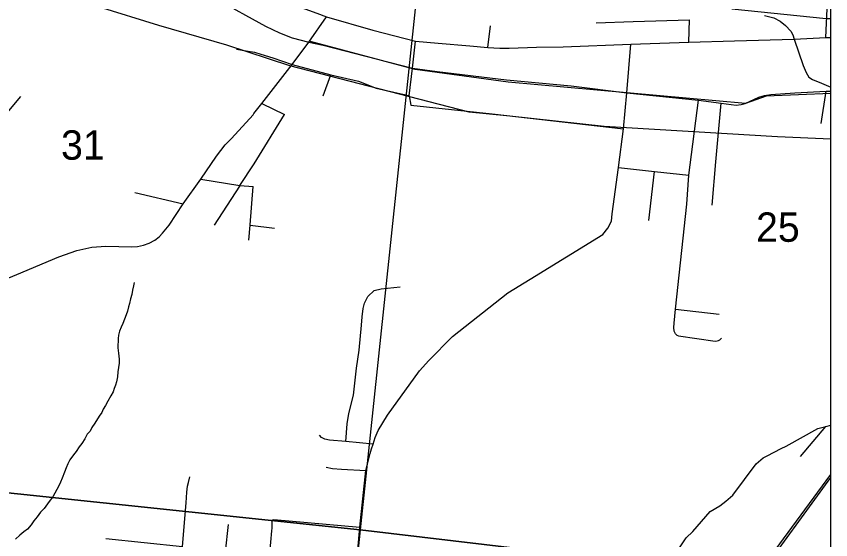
# Model space of a CAD drawing. Extents: x 0 to 34, y -2 to 22.
# Drawn here: x 7.738 to 8.9, y 17.461 to 18.207 of the extents above; entities that cross this region are included whole.
import ezdxf

# ---------------------------------------------------------------- set-up
doc = ezdxf.new("R2010")
doc.units = 0
for name, color, linetype in [('Default', 7, 'Continuous'), ('GM_X_City_Street', 7, 'Continuous'), ('GM_X_County_Road', 7, 'Continuous'), ('GM_X_Minor_River', 7, 'Continuous'), ('GM_X_Rail_Line', 7, 'Continuous'), ('GM_X_Section', 7, 'Continuous'), ('GM_X_Section_Text', 7, 'Continuous'), ('SH_Cut_Line', 7, 'Continuous')]:
    doc.layers.add(name, color=color, linetype=linetype)

msp = doc.modelspace()

# ---------------------------------------------------------------- linework, layer by layer
at = {"layer": 'Default'}
for points in [[(8.9, 17.3957), (8.9, 18.4149), (8.3344, 18.4751), (8.2288, 17.4754)], [(8.9, 16.3966), (8.9, 17.3957), (8.2288, 17.4754), (8.1243, 16.4653), (8.7506, 16.3888), (8.762, 16.3912), (8.7711, 16.3925), (8.792, 16.3947), (8.8076, 16.3958), (8.8333, 16.3964), (8.8504, 16.3971), (8.8879, 16.3966)]]:
    msp.add_lwpolyline(points, close=True, dxfattribs=at)
at = {"layer": 'GM_X_City_Street'}
for p, q in [((8.6978, 18.1706), (8.6983, 18.2023)), ((8.4109, 18.163), (8.4145, 18.1937)), ((8.1757, 18.0942), (8.1869, 18.124)), ((8.8865, 18.0548), (8.8934, 18.1006)), ((8.0882, 18.0833), (8.1208, 18.0673)), ((8.6403, 17.9165), (8.6486, 17.9863)), ((7.9071, 17.9561), (7.976, 17.9398)), ((8.0717, 17.9094), (8.1065, 17.9055)), ((8.6786, 17.7899), (8.7409, 17.7825)), ((8.8569, 17.5799), (8.8929, 17.6226)), ((8.1054, 17.4898), (8.228, 17.4791))]:
    msp.add_line(p, q, dxfattribs=at)
for points in [[(8.8931, 18.1772), (8.8963, 18.2495), (8.898, 18.2736), (8.9, 18.287)], [(8.5652, 18.1982), (8.618, 18.1999), (8.6983, 18.2023)], [(8.2986, 18.0938), (8.3032, 18.1336), (8.3078, 18.1718)], [(8.0523, 18.1605), (8.0658, 18.1581), (8.0778, 18.1565), (8.087, 18.1534), (8.104, 18.1481), (8.1315, 18.1388)], [(8.1315, 18.1388), (8.1869, 18.124), (8.2261, 18.115), (8.2516, 18.1049), (8.2916, 18.0961), (8.2986, 18.0938)], [(7.4663, 17.9186), (7.5384, 17.9251), (7.5903, 17.932), (7.6582, 17.941), (7.6604, 17.9416), (7.6635, 17.9429), (7.6669, 17.9452), (7.6708, 17.9489), (7.6721, 17.9509), (7.6728, 17.953), (7.6765, 17.989), (7.6792, 18.0052), (7.6968, 18.0333), (7.7178, 18.0613), (7.7446, 18.093)], [(8.2986, 18.0938), (8.301, 18.0806), (8.4172, 18.0684), (8.6044, 18.0469)], [(8.6784, 17.7547), (8.6765, 17.7583), (8.6764, 17.7637), (8.6768, 17.7697), (8.6786, 17.7899), (8.6946, 17.9397), (8.6978, 17.981), (8.7112, 18.0877)], [(8.7309, 17.9379), (8.7359, 18.0001), (8.7437, 18.0837)], [(8.021, 17.9098), (8.0568, 17.9654), (8.0572, 17.9661), (8.0772, 17.9971), (8.1208, 18.0673)], [(8.5971, 17.9918), (8.6486, 17.9863), (8.6978, 17.981)], [(8.0015, 17.9753), (8.0572, 17.9661), (8.0761, 17.9649)], [(8.07, 17.8884), (8.0717, 17.9094), (8.0717, 17.9103), (8.0761, 17.9649)], [(8.2084, 17.6013), (8.2101, 17.6265), (8.2125, 17.6411), (8.2193, 17.6672), (8.2236, 17.7057), (8.2273, 17.7313), (8.2306, 17.7672), (8.2314, 17.779), (8.2331, 17.7906), (8.2346, 17.7985), (8.2394, 17.8081), (8.2487, 17.8163), (8.2587, 17.8188), (8.2856, 17.8216)], [(8.6784, 17.7547), (8.6803, 17.7529), (8.683, 17.7517), (8.7353, 17.7443), (8.7379, 17.7445), (8.7398, 17.7451), (8.742, 17.7462), (8.7442, 17.7484)], [(8.6715, 17.4307), (8.6939, 17.4636), (8.7034, 17.473), (8.728, 17.5016), (8.7419, 17.5094), (8.7505, 17.516), (8.7603, 17.5248), (8.7936, 17.5692), (8.8035, 17.578), (8.8091, 17.5808), (8.8295, 17.5911), (8.8365, 17.5947), (8.8814, 17.6198), (8.8929, 17.6226), (8.9, 17.6243)], [(8.247, 17.5975), (8.2084, 17.6013), (8.1849, 17.6031), (8.1781, 17.6047), (8.1737, 17.607), (8.1705, 17.6104)], [(8.1802, 17.5644), (8.1892, 17.5625), (8.2018, 17.5615), (8.2368, 17.5597)], [(7.9504, 17.2143), (7.9504, 17.2176), (7.9509, 17.2234), (7.9607, 17.3157), (7.9752, 17.4513), (7.9806, 17.5136), (7.9813, 17.529), (7.9823, 17.5376), (7.9835, 17.5428), (7.9858, 17.551)], [(8.0612, 17.0667), (8.0744, 17.1973), (8.0848, 17.3028), (8.0991, 17.438), (8.101, 17.4576), (8.1025, 17.4738), (8.103, 17.4777), (8.1031, 17.4832), (8.1031, 17.4872), (8.1038, 17.4894), (8.1054, 17.4898)], [(7.976, 16.871), (7.9973, 17.0616), (7.9992, 17.0743), (8.012, 17.2021), (8.0237, 17.3088), (8.0365, 17.4437), (8.041, 17.4827)], [(7.866, 17.4629), (7.9752, 17.4513)]]:
    msp.add_lwpolyline(points, dxfattribs=at)
at = {"layer": 'GM_X_County_Road'}
for points in [[(8.0322, 18.2591), (8.0709, 18.2467), (8.1167, 18.2299), (8.1666, 18.2118), (8.1804, 18.2065), (8.2466, 18.1876), (8.3078, 18.1718), (8.3397, 18.169), (8.3851, 18.1652), (8.4109, 18.163), (8.4281, 18.1619), (8.4412, 18.1621), (8.4804, 18.1632), (8.5185, 18.164), (8.6148, 18.1677), (8.6978, 18.1706), (8.7625, 18.1723), (8.8479, 18.1749)], [(8.0225, 18.2329), (8.0937, 18.1933), (8.1135, 18.1836), (8.1317, 18.1768), (8.1552, 18.1704)], [(8.8055, 18.2086), (8.8187, 18.2053), (8.828, 18.2007), (8.8357, 18.1945), (8.8431, 18.1862), (8.8461, 18.181), (8.8479, 18.1749)], [(8.0769, 18.0686), (8.0882, 18.0833), (8.1315, 18.1388), (8.1552, 18.1704), (8.1804, 18.2065)], [(8.8479, 18.1749), (8.8931, 18.1772), (8.9, 18.1773)], [(8.8479, 18.1749), (8.8606, 18.1372), (8.8648, 18.1274), (8.869, 18.1207), (8.8741, 18.1171), (8.887, 18.1119), (8.9, 18.1066)], [(8.1552, 18.1704), (8.176, 18.1662), (8.2368, 18.1504), (8.3032, 18.1336), (8.3387, 18.1286), (8.4374, 18.117), (8.5295, 18.1081), (8.6091, 18.0985), (8.7112, 18.0877), (8.7437, 18.0837), (8.765, 18.0808), (8.7723, 18.0815), (8.7778, 18.0829), (8.7975, 18.0921), (8.8054, 18.0945), (8.8145, 18.0961), (8.8487, 18.0984), (8.8934, 18.1006), (8.9, 18.1006)], [(8.2234, 17.4245), (8.228, 17.4791), (8.2368, 17.5597), (8.2428, 17.5841), (8.2448, 17.5909), (8.247, 17.5975), (8.2502, 17.6069), (8.2545, 17.6168), (8.2678, 17.6389), (8.3131, 17.7019), (8.3264, 17.7167), (8.3606, 17.7511), (8.4393, 17.8131), (8.4713, 17.8324), (8.5748, 17.8962), (8.5822, 17.9052), (8.5874, 17.9154), (8.5883, 17.9256), (8.5971, 17.9918), (8.6044, 18.0469), (8.6091, 18.0985), (8.6148, 18.1677)], [(7.7072, 17.8263), (7.7388, 17.8395), (7.7987, 17.8644), (7.8242, 17.8736), (7.846, 17.8783), (7.8659, 17.8797), (7.9027, 17.8786), (7.9111, 17.8794), (7.9193, 17.881), (7.9274, 17.8839), (7.9356, 17.8881), (7.9419, 17.8931), (7.9468, 17.8983), (7.956, 17.9096), (7.976, 17.9398), (8.0015, 17.9753), (8.0236, 18.0081), (8.0362, 18.0242), (8.0451, 18.0334), (8.0758, 18.0671), (8.0769, 18.0686)], [(8.582, 16.7358), (8.5958, 16.7847), (8.6067, 16.8315), (8.613, 16.8584), (8.6291, 16.9179), (8.6344, 16.9724), (8.6414, 17.0222), (8.6589, 17.0461), (8.685, 17.0981), (8.715, 17.1789), (8.7208, 17.199), (8.755, 17.3171), (8.7589, 17.3326), (8.7699, 17.3755), (8.7743, 17.3825), (8.7929, 17.4086), (8.8207, 17.4464), (8.9, 17.5541)]]:
    msp.add_lwpolyline(points, dxfattribs=at)
at = {"layer": 'GM_X_Minor_River'}
msp.add_lwpolyline([(7.9063, 17.8278), (7.9051, 17.8229), (7.9038, 17.8168), (7.9028, 17.8107), (7.9008, 17.8047), (7.8995, 17.7979), (7.8982, 17.793), (7.8965, 17.7869), (7.8948, 17.7816), (7.8899, 17.7696), (7.8875, 17.764), (7.8855, 17.7587), (7.8838, 17.7526), (7.8833, 17.7481), (7.8829, 17.7348), (7.8838, 17.7271), (7.8848, 17.7187), (7.885, 17.713), (7.884, 17.7065), (7.8831, 17.7005), (7.8822, 17.6933), (7.8808, 17.6861), (7.8796, 17.6815), (7.8779, 17.6766), (7.8763, 17.6721), (7.8731, 17.6665), (7.8687, 17.6586), (7.8651, 17.6526), (7.8619, 17.6474), (7.8599, 17.6425), (7.8563, 17.6372), (7.8503, 17.6271), (7.8456, 17.6211), (7.8432, 17.6159), (7.8393, 17.6114), (7.8357, 17.605), (7.8317, 17.5983), (7.8278, 17.5938), (7.8234, 17.5871), (7.8195, 17.5823), (7.8143, 17.5752), (7.8115, 17.5695), (7.8091, 17.5635), (7.8066, 17.5575), (7.8033, 17.5488), (7.8009, 17.5432), (7.7985, 17.5379), (7.7901, 17.5221), (7.7849, 17.5158), (7.7778, 17.5057), (7.7727, 17.5002), (7.768, 17.4938), (7.7629, 17.4879), (7.7593, 17.4822), (7.7542, 17.4763), (7.7488, 17.4726), (7.7433, 17.4678), (7.7371, 17.4619)], dxfattribs=at)
at = {"layer": 'GM_X_Rail_Line'}
for points in [[(7.6912, 15.289), (7.9856, 15.5639), (8.2003, 15.8586), (8.2596, 15.9572), (8.5337, 16.2495), (8.6286, 16.3042), (8.7283, 16.3459), (8.827, 16.358), (8.9, 16.3574), (8.9, 20.9)], [(8.9, 18.0324), (8.8241, 18.0356), (8.5766, 18.0505), (8.4424, 18.0652), (8.3842, 18.0707), (8.1282, 18.1369), (8.0382, 18.1663), (7.9414, 18.1945), (7.8552, 18.2209)], [(8.9, 18.2038), (8.8934, 18.204), (8.7591, 18.2174)], [(8.9, 18.0972), (8.8081, 18.0934), (8.7782, 18.0831), (8.44, 18.1136), (8.3071, 18.1314), (8.156, 18.1718)], [(8.5802, 16.7346), (8.6309, 16.9422), (8.6388, 17.023), (8.6657, 17.0611), (8.697, 17.129), (8.7281, 17.2039), (8.7533, 17.2946), (8.7737, 17.3687), (8.7924, 17.4016), (8.9, 17.55)]]:
    msp.add_lwpolyline(points, dxfattribs=at)
at = {"layer": 'GM_X_Section'}
for points in [[(8.3344, 18.4751), (8.2288, 17.4754), (7.2505, 17.5778), (7.3433, 18.5849)], [(7.2505, 17.5778), (8.2288, 17.4754), (8.1243, 16.4653), (7.1499, 16.5781)]]:
    msp.add_lwpolyline(points, close=True, dxfattribs=at)
at = {"layer": 'SH_Cut_Line'}
msp.add_lwpolyline([(6.0485, 14.702), (6.1464, 14.7771), (6.2416, 14.8366), (6.3391, 14.8719), (6.8207, 14.994), (7.0052, 15.0295), (7.018, 15.0319), (7.3068, 15.0956), (7.4995, 15.1593), (7.5948, 15.214), (7.6912, 15.289), (7.9856, 15.5639), (8.2003, 15.8586), (8.2596, 15.9572), (8.5337, 16.2495), (8.6286, 16.3042), (8.7283, 16.3459), (8.827, 16.358), (8.9, 16.3574), (8.9, 20.9), (2.1, 20.9)], dxfattribs=at)

# ---------------------------------------------------------------- texts
at = {"layer": 'GM_X_Section_Text'}
for s, p in [('31', (7.8019, 18.003)), ('25', (8.7935, 17.8859))]:
    msp.add_text(s, height=0.04186, rotation=0, dxfattribs=at).set_placement(p)

doc.saveas('drawing.dxf')
